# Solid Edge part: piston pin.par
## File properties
Author: Robert a Rhodes jr
Template: Normal.par
Last saved by: CADCIM
Revision: 4
Application: Solid Edge
Accuracy: 0.99
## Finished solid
Body 1: solid body, 4 faces, 4 edges, 0 vertices.
  Faces by surface: cylinder 2, plane 2
  Edges by curve: circle 4
Bounding box of the edges (mm): 22.000 x 22.000 x 80.000, from (-11, -11, -80) to (11, 11, 0).
Cylindrical faces by radius (mm): R5.5 x1, R11 x1
Planar faces by outward normal: +z 1, -z 1
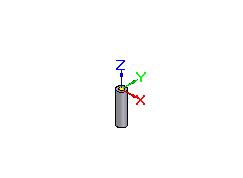
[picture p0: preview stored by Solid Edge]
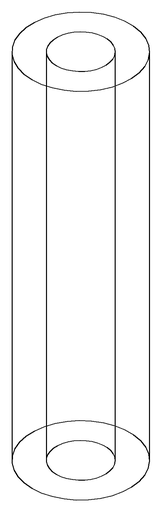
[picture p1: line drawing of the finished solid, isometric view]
